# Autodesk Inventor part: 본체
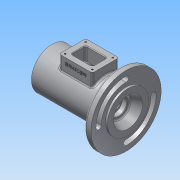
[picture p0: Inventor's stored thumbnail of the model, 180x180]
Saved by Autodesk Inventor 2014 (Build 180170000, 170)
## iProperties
Created: 2017-05
Part Number: 본체
Material: 알루미늄 6061
Document SubType Name: Modeling
Designer: Administrator
Mass: 719.568 g
Surface Area: 634.842 cm^2
Volume: 265.523 cm^3
Density: 2.71 g/cm^3
Appearance: 알루미늄 - 평지
Author: Administrator
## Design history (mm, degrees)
sketch "스케치1"
  geometry: C1 r 31 at (0, 0); 1 further point
  constraints: 1 centre point, 1 coincident
  dimensions: "d0" = 62 diameter of C1
extrude "돌출1" new body sketch "스케치1" stored distance "d1" = 115; taper "d2" = 0 deg
sketch "스케치2"
  geometry: L1 (57.5, 31)-(57.5, -31) reference; L2 (57.5, -31)-(-57.5, -31) reference; L3 (-57.5, -31)-(-57.5, 31) reference; L4 (-57.5, 31)-(57.5, 31) reference; L5 (-57.5, 0)-(57.5, 0); L6 (-48.5, 0)-(-48.5, 24); L7 (-48.5, 24)-(-45.5, 24); L8 (-45.5, 24)-(-45.5, 20); L9 (-45.5, 20)-(-36.5, 20); L10 (-36.5, 20)-(-36.5, 17.5); L11 (-36.5, 17.5)-(-33.25, 17.5); L12 (-31.5, 17.5)-(-31.5, 18.5); L13 (-31.5, 18.5)-(-33.25, 18.5); L14 (-33.25, 18.5)-(-33.25, 17.5); L15 (-31.5, 17.5)-(-21.5, 17.5); L16 (-20.5, 18.5)-(-20.5, 23); L17 (-17.5, 26)-(14.5, 26); L18 (17.5, 23)-(17.5, 18.5); L19 (18.5, 17.5)-(28.2, 17.5); L20 (28.5, 17.2)-(28.5, 16.5); L21 (28.5, 16.5)-(30.5, 16.5); L22 (33.5, 13.5)-(33.5, 10); L23 (33.5, 10)-(36.2, 10); L24 (36.2, 10)-(36.2, 12.2); L25 (36.5, 12.5)-(42.8, 12.5); L26 (43.5, 12.904)-(43.5, 14.022); L27 (45.318, 16.779)-(57.5, 22); L28 (-21.5, 17.5)-(-20.5, 18.5); L29 (42.8, 12.5)-(43.5, 12.904); L30 (17.5, 18.5)-(18.5, 17.5); A1 r 3 centre (-17.5, 23) between (-17.5, 26) and (-20.5, 23); A2 r 3 centre (14.5, 23) between (17.5, 23) and (14.5, 26); A3 r 0.3 centre (28.2, 17.2) between (28.5, 17.2) and (28.2, 17.5); A4 r 3 centre (30.5, 13.5) between (33.5, 13.5) and (30.5, 16.5); A5 r 0.3 centre (36.5, 12.2) between (36.5, 12.5) and (36.2, 12.2); A6 r 3 centre (46.5, 14.022) between (45.318, 16.779) and (43.5, 14.022); 12 further points
  constraints: 52 end point, 20 point on line, 19 parallel, 12 point on circle, 12 tangent, 6 centre point, 4 midpoint, 2 perpendicular, 1 equal radius, 1 horizontal alignment
  dimensions: "d3" = 48 diameter of L7 L5; "d5" = 12 horizontal distance of L7.end L3.end; "d6" = 3 distance between parallel lines of L8 L6; "d7" = 21 distance between parallel lines of L10 L3; "d9" = 26 distance between parallel lines of L3 L12; "d10" = 1.75 distance between parallel lines of L12 L14; "d11" = 40 diameter of L9 L5; "d12" = 35 diameter of L11 L5; "d13" = 37 diameter of L13 L5; "d14" = 11 distance from line of L16 L12.start; "d15" = 52 diameter of L17 L5; "d16" = 38 distance between parallel lines of L18 L16; "d18" = 35 diameter of L19 L5; "d19" = 11 distance of point (17.5, 17.5) point (28.5, 17.5); "d20" = 33 diameter of L21 L5; "d21" = 5 distance of L20.end point (33.5, 16.5); "d22" = 2.7 distance of L22.end L23.end; "d23" = 20 diameter of L23 L5; "d24" = 25 diameter of L25 L5; "d25" = 7.3 distance of point (36.2, 12.5) point (43.5, 12.5); "d26" = 32 diameter of point (43.5, 16) L5; "d27" = 44 diameter of L27.end L5; "d29" = 1 distance of L15.end point (-20.5, 17.5); "d30" = 1 distance of L16.start point (-20.5, 17.5) (= d29); "d31" = 3 radius of A1; "d32" = 0.3 radius of A3; "d33" = 3 radius of A4; "d34" = 0.3 radius of A5; "d35" = 0.7 distance of L25.end point (43.5, 12.5); "d36" = 30 deg angle of L25 L29; "d37" = 3 radius of A6; "d96" = 1 distance of L18.end point (17.5, 17.5); "d97" = 1 distance of L19.start point (17.5, 17.5) (= d96)
revolve "회전1" sketch "스케치2" stored, may be unused: angle "d28" = 90 deg
hole "구멍1" diameter "d40" = 40.376; stored, may be unused: countersink angle "d44" = 90 deg, drill point angle "d46" = 0 deg; dims "d38" = 10, "d39" = 10, "d41" = 6, "d42" = 4, "d43" = 2, "d45" = 9
node "작업 평면1"
sketch "스케치4"
  geometry: C1 r 53 at (0, 0); C2 r 20.714 at (0, 0) reference; C3 r 31 at (0, 0) reference; 1 further point
  constraints: 1 centre point, 1 coincident
  dimensions: "d48" = 106 diameter of C1
extrude "돌출2" join sketch "스케치4" distance "d49" = 10; taper "d50" = 0 deg
fillet "모깎기1" dims "d51" = 3
sketch "스케치5"
  geometry: C1 r 31 at (0, 0) reference; C2 r 50 at (0, 0) reference; A1 r 41.5 centre (0, 0) between (0, 41.5) and (-41.5, 0); A2 r 4 centre (0, 41.5) between (0, 37.5) and (0, 45.5); A3 r 4 centre (-41.5, 0) between (-45.5, 0) and (-37.5, 0); A4 r 37.5 centre (0, 0) between (0, 37.5) and (-37.5, 0); A5 r 45.5 centre (0, 0) between (0, 45.5) and (-45.5, 0)
  constraints: 10 point on circle, 5 centre point, 2 coincident, 1 horizontal alignment, 1 tangent, 1 vertical alignment
  dimensions: "d52" = 83 diameter of A1; "d53" = 8 diameter of A2; "d54" = 8 diameter of A3; "d55" = 4 radial gap between concentric circles of A5 A1
extrude "돌출3" cut sketch "스케치5" stored distance "d56" = 13; taper "d57" = 0 deg
node "작업 평면2"
sketch "스케치6"
  geometry: L1 (-23.5, 20)-(26.5, 20); L2 (26.5, 20)-(26.5, -20); L3 (26.5, -20)-(-23.5, -20); L4 (-23.5, -20)-(-23.5, 20); L5 (57.5, -31)-(57.5, 31) reference; L6 (-23.5, 0)-(26.5, 0); L7 (1.5, 20)-(1.5, -20); 1 further point
  constraints: 12 end point, 4 midpoint, 2 parallel, 2 perpendicular, 1 horizontal, 1 horizontal alignment
  dimensions: "d62" = 50 distance of L1.start L1.end; "d63" = 40 distance of L1.end L2.end; "d65" = 56 distance between parallel lines of L5 L7
extrude "돌출4" join sketch "스케치6" stored distance "d66" = 13; taper "d67" = 0 deg
sketch "스케치8"
  geometry: L1 (-23.5, 20)-(26.5, 20) reference; L2 (-23.5, -20)-(-23.5, 20) reference; L3 (26.5, -20)-(-23.5, -20) reference; L4 (26.5, 20)-(26.5, -20) reference; L5 (1.5, 20)-(1.5, -20); L6 (-23.5, 0)-(26.5, 0); L7 (-14.5, -11)-(17.5, -11); L8 (17.5, -11)-(17.5, 11); L9 (17.5, 11)-(-14.5, 11); L10 (-14.5, 11)-(-14.5, -11); L11 (-14.5, -11)-(17.5, 11); L12 (17.5, -11)-(-14.5, 11); 2 further points
  constraints: 16 end point, 7 midpoint, 2 parallel, 1 horizontal, 1 perpendicular
  dimensions: "d68" = 32 distance of L9.end L8.end; "d69" = 22 distance of L8.end L7.end
extrude "돌출5" cut sketch "스케치8" stored distance "d70" = 13; taper "d71" = 0 deg
sketch "스케치9"
  geometry: L1 (-23.5, 20)-(26.5, 20) reference; L2 (-23.5, -20)-(-23.5, 20) reference; L3 (26.5, -20)-(-23.5, -20) reference; L4 (26.5, 20)-(26.5, -20) reference; L5 (1.5, 20)-(1.5, -20); L6 (-23.5, 0)-(26.5, 0); 2 further points
  constraints: 4 end point, 4 midpoint
  dimensions: "d72" = 20.5 distance from line of L5 point (-19, -15.5); "d73" = 15.5 distance from line of point (-19, -15.5) L6
hole "구멍2" sketch "스케치9" at (-19, -15.5) diameter "d74" = 2.459; stored, may be unused: countersink angle "d78" = 90 deg, drill point angle "d80" = 118 deg; dims "d75" = 6, "d76" = 4, "d77" = 2, "d79" = 8
fillet "모깎기3" dims "d88" = 3
fillet "모깎기4" dims "d89" = 1
node "작업 평면3"
sketch "스케치10"
  geometry: L1 (81, 13)-(81, 75) reference; L2 (0, 0)-(50, 0) reference; 3 further points
  constraints: 1 coincident, 1 other
  dimensions: "d91" = 56 distance from line of point (25, 8) L1; "d92" = 8 distance from line of L2 point (25, 8)
feature "엠보싱1" sketch "스케치10" dims "d93" = 0.5, "d94" = 0
fillet "모깎기5" dims "d95" = 3
node "솔리드1"
pattern_circular "원형 패턴1" dims angle "d59" = 360 deg
pattern_linear "직사각형 패턴1" dims "d83" = 41, "d86" = 31
node "절단 모서리 투영1"
node "절단 모서리 투영2"
other parameters: "d47" = -3, "d61" = 44
